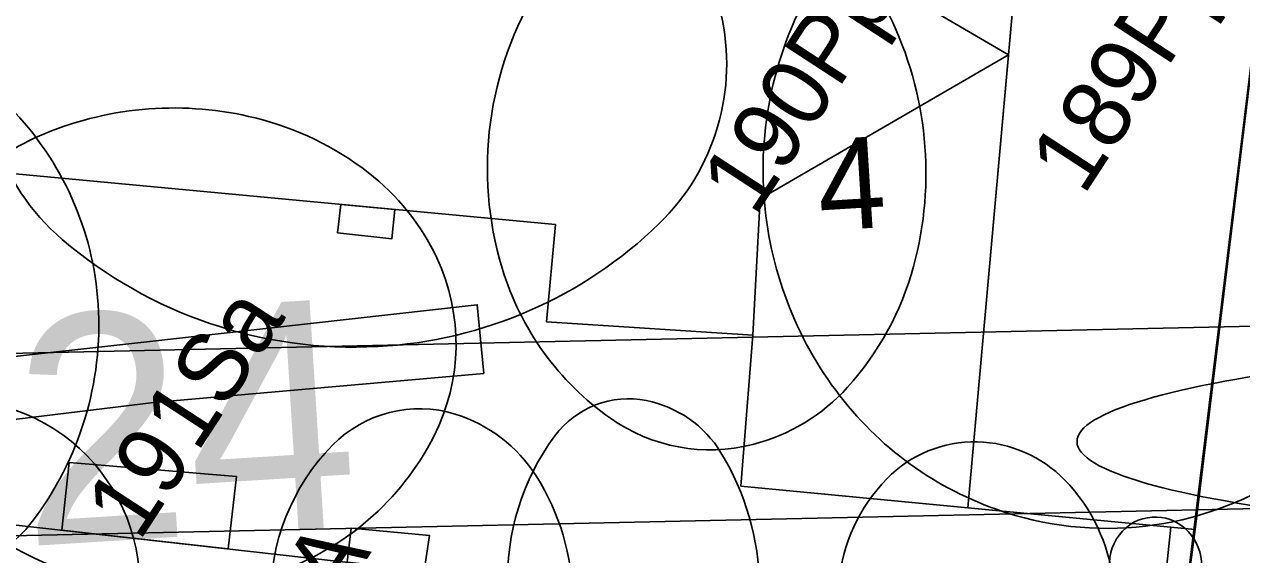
# Model space of a CAD drawing. Extents: x 738423 to 738903, y 6589762 to 6590172.
# Drawn here: x 738605.51 to 738632.2, y 6589882.68 to 6589894.31 of the extents above; entities that cross this region are included whole.
import ezdxf

# ---------------------------------------------------------------- set-up
doc = ezdxf.new("R2010")
doc.units = 0
for name, color, linetype in [('_1927_hoonestus', 7, 'Continuous'), ('_1927_katuse_kalded', 7, 'Continuous'), ('_1927_koordin_punktid_nr', 7, 'Continuous'), ('_1927_krundi_piir', 7, 'Continuous'), ('_1927_kvartali_nr_planžetil', 7, 'Continuous'), ('a_dendro_III_vk_puu', 7, 'Continuous'), ('a_dendro_puu_nr', 7, 'Continuous'), ('a_dendro_V_vk_puu', 7, 'Continuous'), ('Default', 7, 'Continuous'), ('v_olol_kitsendus_tehnov', 7, 'Continuous'), ('v_olol_transp_jjt_jalg', 7, 'Continuous')]:
    doc.layers.add(name, color=color, linetype=linetype)

# ---------------------------------------------------------------- blocks, each defined once
blk = doc.blocks.new('_U594')
at = {"layer": 'Default'}
for centre, radius, start, end in [((0.0004283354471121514, -0.0021435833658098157), 0.008211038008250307, 96.61449276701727, 136.420070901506), ((0.0004289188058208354, -0.002148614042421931), 0.008216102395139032, 57.79749724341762, 96.61449276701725), ((0.0005495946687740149, -0.0019570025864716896), 0.007989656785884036, 18.411864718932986, 57.79749724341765), ((0.00025976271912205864, -0.0019831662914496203), 0.007978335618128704, 136.420070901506, 176.82690828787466), ((0.0006022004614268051, -0.0019394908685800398), 0.007934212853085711, 325.0458822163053, 18.411864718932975), ((0.0002133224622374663, -0.001980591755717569), 0.007931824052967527, 176.82690828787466, 225.10763019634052), ((0.0003884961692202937, -0.001790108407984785), 0.008194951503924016, 272.60163737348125, 325.04588221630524), ((0.0003891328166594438, -0.001804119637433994), 0.00818092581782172, 225.10763019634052, 272.60163737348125)]:
    blk.add_arc(centre, radius, start, end, dxfattribs=at)
blk = doc.blocks.new('_U595')
at = {"layer": 'Default'}
for centre, radius, start, end in [((0.00026917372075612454, -0.0013989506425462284), 0.009452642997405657, 95.68808763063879, 143.604930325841), ((0.0002691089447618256, -0.0013983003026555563), 0.009451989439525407, 49.77799837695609, 95.68808763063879), ((0.0029283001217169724, 0.001745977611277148), 0.0053340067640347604, 347.2248747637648, 49.77799837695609), ((-0.0030518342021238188, 0.0010490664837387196), 0.005326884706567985, 143.604930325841, 209.09949174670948), ((0.0018408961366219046, 0.0019925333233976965), 0.006449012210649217, 306.6745500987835, 347.2248747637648), ((-0.0019871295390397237, 0.0016416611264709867), 0.006545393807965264, 209.09949174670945, 245.76754569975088), ((-0.000487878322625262, 0.0051197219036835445), 0.010348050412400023, 274.9217856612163, 306.67455009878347), ((-0.00047724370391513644, 0.004996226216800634), 0.010224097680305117, 245.76754569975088, 274.9217856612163)]:
    blk.add_arc(centre, radius, start, end, dxfattribs=at)
blk = doc.blocks.new('_U596')
at = {"layer": 'Default'}
for centre, radius, start, end in [((0.0006475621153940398, -0.0044190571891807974), 0.010496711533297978, 96.37245995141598, 136.4200708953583), ((0.000654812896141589, -0.004483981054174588), 0.01056203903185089, 57.79749723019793, 96.37245995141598), ((0.004142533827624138, 0.0010538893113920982), 0.004017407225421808, 353.0316710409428, 57.79749723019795), ((-0.004078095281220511, 7.796995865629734e-05), 0.003973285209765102, 136.4200708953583, 204.05421686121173), ((0.00320223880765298, 0.0011688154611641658), 0.004964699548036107, 305.6591723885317, 353.0316710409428), ((-0.003092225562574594, 0.0005180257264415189), 0.005052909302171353, 204.05421686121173, 246.9121132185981), ((-0.0006592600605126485, 0.006550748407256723), 0.011588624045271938, 275.16957435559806, 305.6591723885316), ((-0.0006349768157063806, 0.006282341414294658), 0.011319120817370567, 246.91211321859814, 275.16957435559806)]:
    blk.add_arc(centre, radius, start, end, dxfattribs=at)
blk = doc.blocks.new('_U597')
at = {"layer": 'Default'}
for centre, radius, start, end in [((-0.0006259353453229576, -0.001909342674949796), 0.007922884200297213, 89.21566834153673, 136.42007090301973), ((-0.0006206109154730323, -0.0015204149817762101), 0.007533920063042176, 49.93101198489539, 89.21566834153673), ((0.0007704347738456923, 0.00013332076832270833), 0.005372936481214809, 3.018713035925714, 49.93101198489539), ((-0.002408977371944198, -0.00021256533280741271), 0.0054615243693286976, 136.42007090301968, 194.08345184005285), ((0.0006276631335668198, 0.00012579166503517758), 0.005515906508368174, 318.450141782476, 3.018713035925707), ((-0.002175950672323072, -0.00015410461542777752), 0.0057017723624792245, 194.08345184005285, 241.43290441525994), ((-0.0010188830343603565, 0.0015850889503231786), 0.00771605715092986, 281.050080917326, 318.450141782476), ((-0.0010743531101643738, 0.0018691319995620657), 0.008005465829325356, 241.4329044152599, 281.050080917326)]:
    blk.add_arc(centre, radius, start, end, dxfattribs=at)
blk = doc.blocks.new('_U598')
at = {"layer": 'Default'}
for centre, radius, start, end in [((7.664831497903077e-05, -0.00010094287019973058), 0.002145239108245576, 97.86846226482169, 154.19372936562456), ((7.65283049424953e-05, -0.00010007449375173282), 0.002144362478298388, 51.0916762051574, 97.86846226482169), ((0.00019917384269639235, 5.1876611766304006e-05), 0.001949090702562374, 1.8801261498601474, 51.09167620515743), ((-0.00010340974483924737, -1.3875090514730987e-05), 0.0019452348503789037, 154.1937293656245, 213.6184524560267), ((0.0001533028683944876, 5.037084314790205e-05), 0.0019949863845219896, 316.77867124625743, 1.8801261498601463), ((-4.770564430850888e-05, 2.316048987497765e-05), 0.002012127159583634, 213.6184524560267, 244.2463257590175), ((1.6170534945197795e-05, 0.00017924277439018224), 0.0021831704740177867, 273.7664575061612, 316.7786712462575), ((1.7541957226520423e-05, 0.00015841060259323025), 0.0021622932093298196, 244.2463257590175, 273.7664575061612)]:
    blk.add_arc(centre, radius, start, end, dxfattribs=at)
blk = doc.blocks.new('_U638')
at = {"layer": 'Default'}
for centre, radius, start, end in [((0.0017967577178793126, -0.006086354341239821), 0.016298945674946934, 62.43823725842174, 99.23130900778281), ((0.0017785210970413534, -0.00597414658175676), 0.01618526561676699, 99.23130900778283, 132.97828324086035), ((0.002383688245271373, -0.0049618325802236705), 0.015030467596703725, 24.06586474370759, 62.43823725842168), ((0.0009222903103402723, -0.005055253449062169), 0.014929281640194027, 132.97828324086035, 168.16056229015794), ((0.0028454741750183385, -0.004755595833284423), 0.014524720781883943, 325.34619089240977, 24.065864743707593), ((0.00048369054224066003, -0.004963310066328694), 0.0144811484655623, 168.16056229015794, 220.24997545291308), ((0.0015713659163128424, -0.003874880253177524), 0.016073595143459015, 269.78694623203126, 325.3461908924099), ((0.0015707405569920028, -0.004043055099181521), 0.01590541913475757, 220.24997545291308, 269.78694623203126)]:
    blk.add_arc(centre, radius, start, end, dxfattribs=at)
blk = doc.blocks.new('_U639')
at = {"layer": 'Default'}
for centre, radius, start, end in [((0.004641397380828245, -0.004188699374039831), 0.015204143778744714, 62.43823725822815, 111.04298782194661), ((0.003648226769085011, -0.001607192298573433), 0.01243817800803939, 111.04298782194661, 149.17299109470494), ((0.007830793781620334, 0.0019219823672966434), 0.008311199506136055, 354.7908139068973, 62.43823725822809), ((-0.0005217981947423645, 0.0008813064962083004), 0.007582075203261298, 149.1729910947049, 198.6357057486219), ((0.006724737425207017, 0.002022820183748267), 0.00942184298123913, 300.55754800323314, 354.7908139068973), ((0.0002487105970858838, 0.0011411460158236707), 0.008395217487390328, 198.63570574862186, 232.2443045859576), ((0.00306019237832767, 0.004771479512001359), 0.012986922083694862, 232.24430458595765, 259.1261887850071), ((0.0035614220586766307, 0.0073807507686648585), 0.015643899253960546, 259.1261887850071, 300.55754800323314)]:
    blk.add_arc(centre, radius, start, end, dxfattribs=at)
blk = doc.blocks.new('_U640')
at = {"layer": 'Default'}
for centre, radius, start, end in [((-0.004594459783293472, 0.00634823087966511), 0.009284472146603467, 68.51192982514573, 143.64928581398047), ((-0.005333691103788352, 0.004470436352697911), 0.011302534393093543, 26.702830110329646, 68.51192982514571), ((-0.000739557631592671, 0.00351126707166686), 0.01407076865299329, 143.64928581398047, 203.0247562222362), ((-0.008475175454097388, 0.002890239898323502), 0.01481905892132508, 350.38975327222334, 26.702830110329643), ((-0.007040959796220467, 0.002647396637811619), 0.013364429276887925, 326.6578135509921, 350.38975327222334), ((-0.002513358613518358, 0.0027574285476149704), 0.012143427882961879, 203.0247562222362, 247.27144465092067), ((-0.004425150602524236, 0.0009263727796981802), 0.010233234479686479, 299.47632079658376, 326.6578135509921), ((-0.003767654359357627, -0.0002368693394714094), 0.008897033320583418, 247.2714446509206, 299.47632079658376)]:
    blk.add_arc(centre, radius, start, end, dxfattribs=at)
blk = doc.blocks.new('_U641')
at = {"layer": 'Default'}
for centre, radius, start, end in [((0.00018620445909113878, -0.009268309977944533), 0.015297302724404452, 92.63657207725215, 125.0968102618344), ((0.00015016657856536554, -0.008485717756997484), 0.014513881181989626, 63.54258914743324, 92.63657207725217), ((0.003371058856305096, -0.0020135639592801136), 0.0072845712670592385, 22.012165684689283, 63.54258914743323), ((-0.004347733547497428, -0.0028164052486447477), 0.007411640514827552, 125.09681026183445, 172.44541812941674), ((0.004561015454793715, -0.0015324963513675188), 0.00600105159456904, 318.79140361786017, 22.012165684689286), ((-0.005593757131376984, -0.0026511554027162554), 0.006154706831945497, 172.44541812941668, 236.85170051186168), ((-0.0011128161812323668, 0.003436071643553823), 0.013542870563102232, 277.95083119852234, 318.79140361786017), ((-0.0012018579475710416, 0.004073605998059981), 0.014186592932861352, 236.8517005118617, 277.95083119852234)]:
    blk.add_arc(centre, radius, start, end, dxfattribs=at)
blk = doc.blocks.new('_U662')
at = {"layer": 'Default'}
for centre, radius, start, end in [((-0.0028954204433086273, 0.006266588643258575), 0.009853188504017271, 80.49660816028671, 143.76371603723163), ((-0.0031717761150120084, 0.004615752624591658), 0.011526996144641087, 36.73116785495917, 80.49660816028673), ((0.0050267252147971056, 0.00046074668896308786), 0.019675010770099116, 143.76371603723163, 187.3383291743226), ((-0.0105701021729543, -0.0009050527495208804), 0.020758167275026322, 4.4809080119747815, 36.731167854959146), ((-0.010286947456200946, -0.0008828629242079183), 0.020474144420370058, 331.8756544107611, 4.48090801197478), ((0.00450953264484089, 0.0003941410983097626), 0.01915354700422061, 187.3383291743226, 228.46175316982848), ((-0.0021317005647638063, -0.0052418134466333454), 0.011227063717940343, 287.32246647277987, 331.8756544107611), ((-0.00170251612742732, -0.006617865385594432), 0.00978563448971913, 228.46175316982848, 287.32246647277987)]:
    blk.add_arc(centre, radius, start, end, dxfattribs=at)

msp = doc.modelspace()

# ---------------------------------------------------------------- linework, layer by layer
at = {"layer": '_1927_hoonestus'}
for points in [[(738598.7561479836, 6589884.064893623), (738598.7561479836, 6589884.064893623), (738600.1654182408, 6589891.510843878), (738617.1576277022, 6589889.916511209), (738616.9587005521, 6589887.781161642), (738616.9587005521, 6589887.781161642), (738621.4793553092, 6589887.4869466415), (738621.2187353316, 6589884.178665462), (738631.1763472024, 6589883.225550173), (738634.3211426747, 6589909.080822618), (738624.2071897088, 6589909.313105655), (738622.5673353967, 6589895.324185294), (738590.9372064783, 6589898.13516685), (738590.9372064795, 6589898.13516685), (738586.1827055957, 6589872.62061175), (738613.3249623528, 6589869.722398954), (738613.2710881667, 6589869.728151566), (738614.3523733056, 6589877.812429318), (738614.3523733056, 6589877.812429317), (738614.3523733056, 6589877.812429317), (738615.0233334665, 6589882.235576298)], [(738612.4527027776, 6589890.357961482), (738612.3775566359, 6589889.736273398), (738613.5713597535, 6589889.604368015), (738613.6306287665, 6589890.2474398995)], [(738606.4948714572, 6589884.698324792), (738606.3344555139, 6589883.212679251), (738609.9834031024, 6589882.802338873), (738610.1616946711, 6589884.387794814)], [(738612.5896232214, 6589882.509257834), (738612.676152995, 6589883.253722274), (738614.394608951, 6589883.098851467), (738614.2760782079, 6589882.319608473)], [(738630.3069916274, 6589880.082885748), (738630.6451262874, 6589883.276397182), (738631.1763472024, 6589883.225550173), (738630.7554073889, 6589880.026345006)]]:
    msp.add_lwpolyline(points, close=True, dxfattribs=at)
at = {"layer": '_1927_katuse_kalded'}
for points in [[(738634.3211545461, 6589909.080822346), (738627.9783805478, 6589903.577252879), (738626.1975412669, 6589883.702107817), (738631.1763472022, 6589883.225550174)], [(738627.9783805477, 6589903.57725288), (738625.4909918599, 6589900.462473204), (738625.0359812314, 6589894.845607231), (738627.0879609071, 6589893.639680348)], [(738627.0879609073, 6589893.639680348), (738621.6427022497, 6589890.483882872), (738621.4793553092, 6589887.4869466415), (738621.2187353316, 6589884.178665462), (738626.1975412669, 6589883.702107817)], [(738607.6489657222, 6589876.64007853), (738592.8326743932, 6589878.444908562), (738598.7561479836, 6589884.064893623), (738615.023333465, 6589882.235576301)]]:
    msp.add_lwpolyline(points, close=True, dxfattribs=at)
at = {"layer": '_1927_krundi_piir'}
msp.add_lwpolyline([(738638.2396178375, 6589940.94571321), (738636.5091918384, 6589926.8911045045), (738634.3211426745, 6589909.080822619), (738629.2817413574, 6589868.018556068)], dxfattribs=at)
at = {"layer": 'a_dendro_V_vk_puu'}
msp.add_ellipse((738647.6051953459, 6589885.222999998), major_axis=(19.017612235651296, 0.06685041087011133), ratio=0.12347597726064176, dxfattribs=at)
at = {"layer": 'v_olol_kitsendus_tehnov'}
msp.add_lwpolyline([(738586.6888850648, 6589865.143953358), (738591.9451522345, 6589864.37135473), (738592.5597488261, 6589882.810896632), (738660.2059563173, 6589884.29620018), (738660.0179515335, 6589895.618846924), (738656.018502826, 6589895.552438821), (738656.1404538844, 6589888.2078982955), (738592.1413769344, 6589886.802674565), (738592.1718913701, 6589887.668806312), (738591.66193984, 6589894.040728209), (738588.6389999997, 6589893.962)], dxfattribs=at)
at = {"layer": 'v_olol_transp_jjt_jalg'}
msp.add_lwpolyline([(738581.6950000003, 6589884.280999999), (738581.8219999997, 6589883.063999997), (738591.5299999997, 6589883.9679999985), (738608.3539999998, 6589886.010999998), (738615.5839999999, 6589886.649999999), (738615.4390000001, 6589888.155999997), (738608.0640000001, 6589887.33), (738591.8460000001, 6589885.529)], close=True, dxfattribs=at)

# ---------------------------------------------------------------- block references
at = {"layer": 'a_dendro_III_vk_puu', "xscale": 500.0000000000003, "yscale": 500.0000000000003, "rotation": 85.69234851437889}
for name, p in [('_U662', (738612.7799999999, 6589894.540999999)), ('_U638', (738626.7529999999, 6589890.438999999)), ('_U639', (738621.0009999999, 6589888.994)), ('_U641', (738602.1270000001, 6589888.160999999)), ('_U640', (738610.5499999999, 6589889.181000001)), ('_U594', (738603.0383105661, 6589881.864442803)), ('_U596', (738619.1259999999, 6589881.98)), ('_U595', (738614.932310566, 6589881.684442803)), ('_U597', (738626.379, 6589882.074999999))]:
    msp.add_blockref(name, p, dxfattribs=at)
at = {"layer": 'a_dendro_V_vk_puu', "xscale": 500.0000000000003, "yscale": 500.0000000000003, "rotation": 85.69234851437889}
msp.add_blockref('_U598', (738630.316, 6589882.426), dxfattribs=at)

# ---------------------------------------------------------------- texts
at = {"layer": '_1927_koordin_punktid_nr'}
msp.add_text('4', height=1.9999999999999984, rotation=3.560863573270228, dxfattribs=at).set_placement((738622.9569861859, 6589889.773111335))
at = {"layer": '_1927_kvartali_nr_planžetil'}
msp.add_text('24', height=4.999999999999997, rotation=3.560863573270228, dxfattribs=at).set_placement((738605.492384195, 6589882.856226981))
at = {"layer": 'a_dendro_puu_nr'}
for s, rotation, p in [('189Pp', 56.88665020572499, (738628.7303964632, 6589890.528860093)), ('190Pp', 56.88665020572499, (738621.5220221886, 6589890.065686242)), ('1Sa', 56.88665020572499, (738609.3017020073, 6589884.891903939)), ('19', 56.88665020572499, (738608.0283750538, 6589882.9396188)), ('KsA', 57.407585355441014, (738611.1483375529, 6589879.642136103))]:
    msp.add_text(s, height=1.5000000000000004, rotation=rotation, dxfattribs=at).set_placement(p)

doc.saveas('drawing.dxf')
